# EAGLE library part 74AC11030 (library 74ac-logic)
8-input NAND
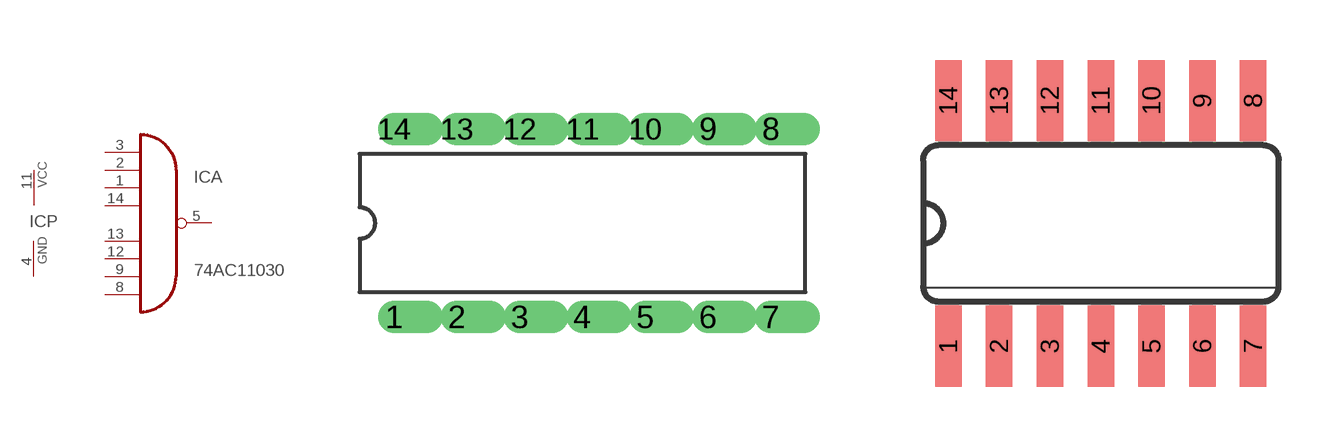
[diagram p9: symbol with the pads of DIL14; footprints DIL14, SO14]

Designator prefix IC; gates A=7411030 P=PWRN

## 74AC11030  [DIL14]
1  A:I2  in
2  A:I1  in
3  A:I0  in
4  P:GND  pwr
5  A:O  out
8  A:I7  in
9  A:I6  in
11  P:VCC  pwr
12  A:I5  in
13  A:I4  in
14  A:I3  in

## 74AC11030D  [SO14]
Pads as for DIL14

## Footprint DIL14 (pad centres in mm)
Dual In Line
drill 0.813 offset: 1 -7.62,-3.81; 2 -5.08,-3.81; 3 -2.54,-3.81; 4 0,-3.81; 5 2.54,-3.81; 6 5.08,-3.81; 7 7.62,-3.81; 8 7.62,3.81; 9 5.08,3.81; 10 2.54,3.81; 11 0,3.81; 12 -2.54,3.81; 13 -5.08,3.81; 14 -7.62,3.81

## Footprint SO14 (pad centres in mm)
Small Outline package 150 mil
smd 0.66 x 2.032: 1 -3.81,-3.073; 2 -2.54,-3.073; 3 -1.27,-3.073; 4 0,-3.073; 5 1.27,-3.073; 6 2.54,-3.073; 7 3.81,-3.073; 8 3.81,3.073; 9 2.54,3.073; 10 1.27,3.073; 11 0,3.073; 12 -1.27,3.073; 13 -2.54,3.073; 14 -3.81,3.073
